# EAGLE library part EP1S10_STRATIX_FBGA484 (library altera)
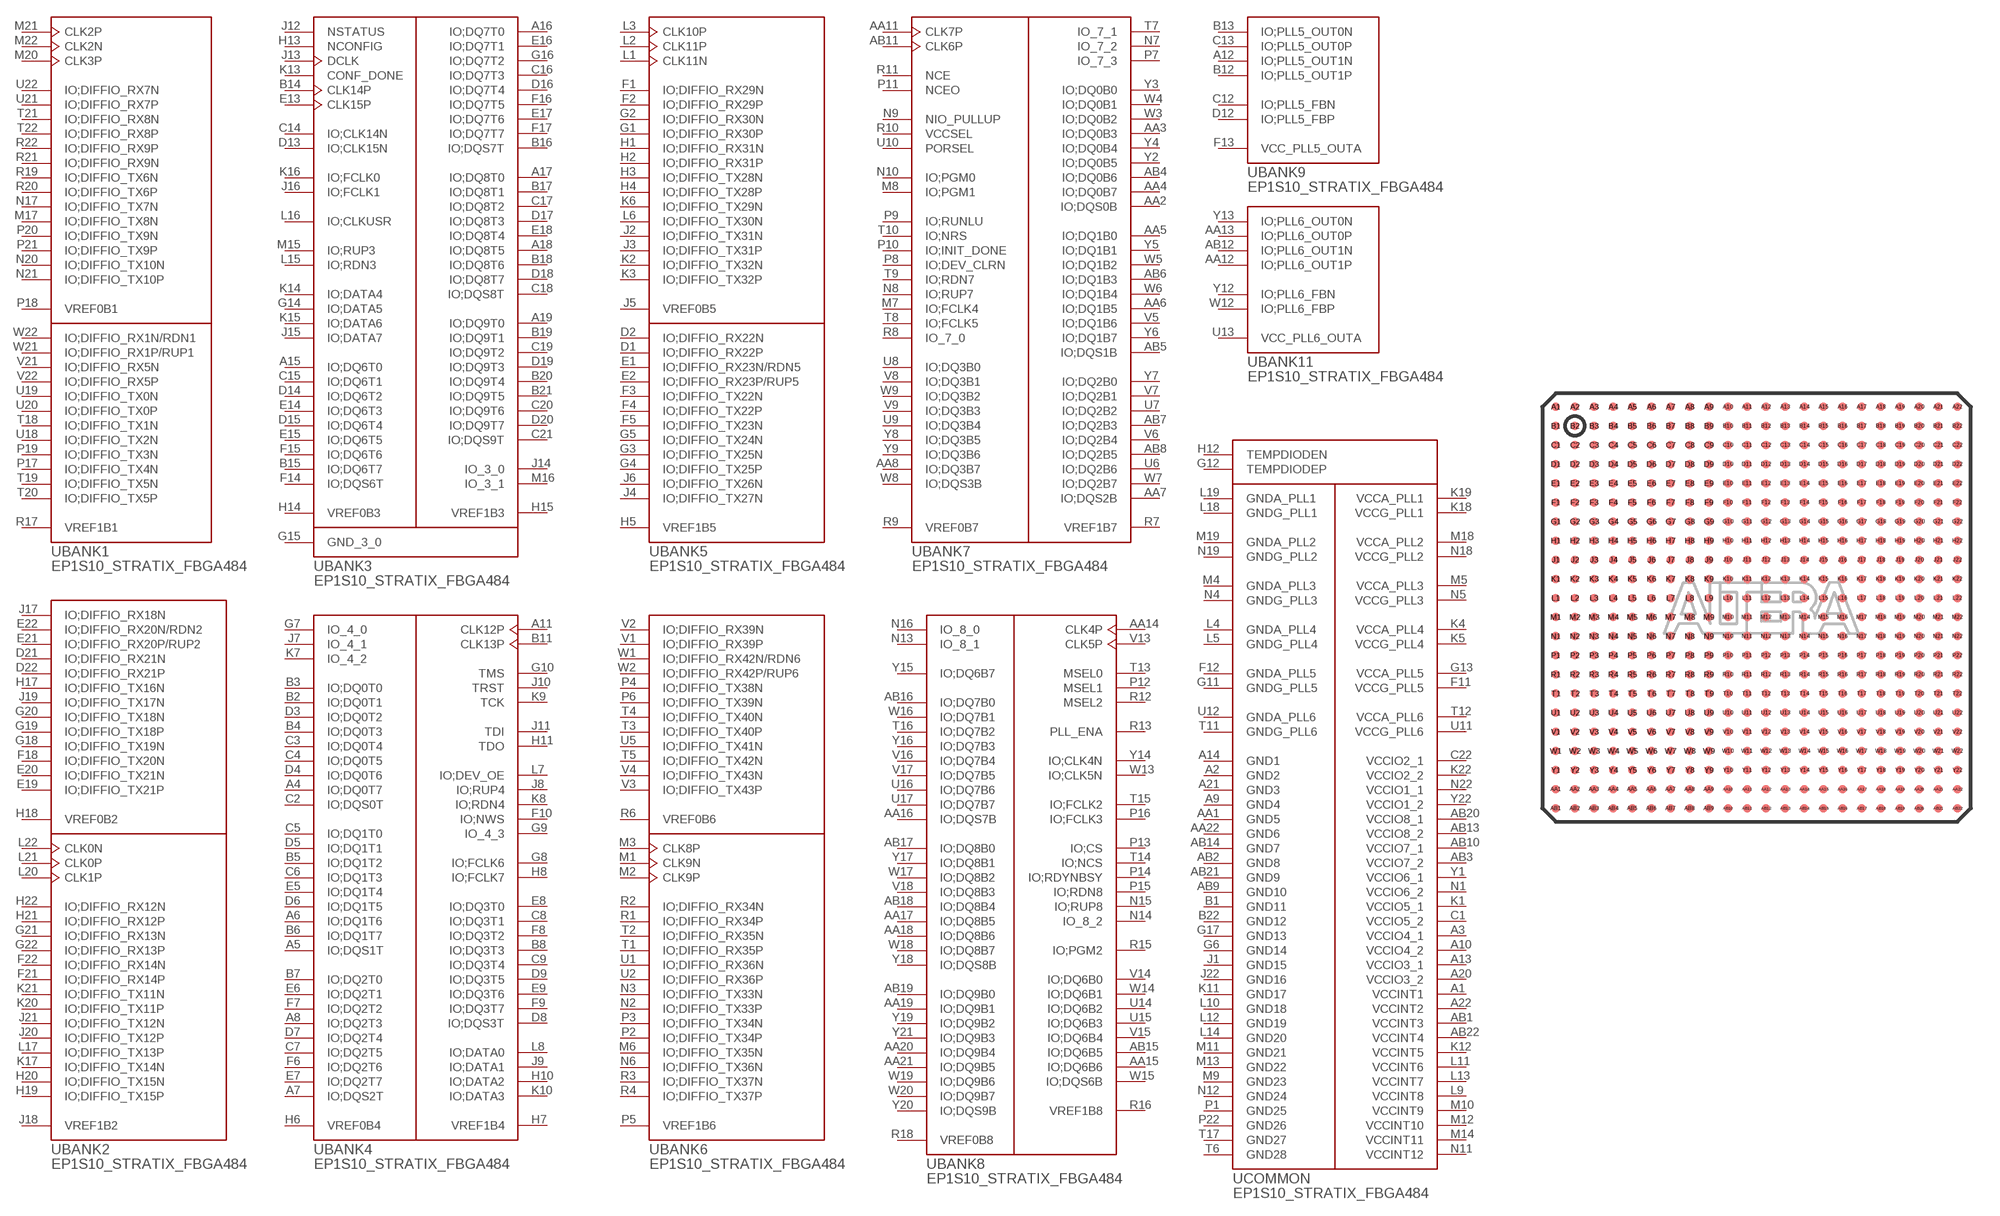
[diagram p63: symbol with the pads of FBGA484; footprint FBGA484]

Designator prefix -; gates COMMON=EP1S10_FBGA484_0 BANK1=EP1S10_FBGA484_1 BANK2=EP1S10_FBGA484_2 BANK3=EP1S10_FBGA484_3 BANK4=EP1S10_FBGA484_4 BANK5=EP1S10_FBGA484_5 BANK6=EP1S10_FBGA484_6 BANK7=EP1S10_FBGA484_7 BANK8=EP1S10_FBGA484_8 BANK9=EP1S10_FBGA484_9 BANK11=EP1S10_FBGA484_11 NC=EP1S10_FBGA484_NC

## EP1S10_STRATIX_FBGA484  [FBGA484]
A1  COMMON:VCCINT1  pwr
A2  COMMON:GND2  pwr
A3  COMMON:VCCIO4_1  pwr
A4  BANK4:IO;DQ0T7
A5  BANK4:IO;DQS1T
A6  BANK4:IO;DQ1T6
A7  BANK4:IO;DQS2T
A8  BANK4:IO;DQ2T3
A9  COMMON:GND4  pwr
A10  COMMON:VCCIO4_2  pwr
A11  BANK4:CLK12P  in
A12  BANK9:IO;PLL5_OUT1N
A13  COMMON:VCCIO3_1  pwr
A14  COMMON:GND1  pwr
A15  BANK3:IO;DQ6T0
A16  BANK3:IO;DQ7T0
A17  BANK3:IO;DQ8T0
A18  BANK3:IO;DQ8T5
A19  BANK3:IO;DQ9T0
A20  COMMON:VCCIO3_2  pwr
A21  COMMON:GND3  pwr
A22  COMMON:VCCINT2  pwr
AA1  COMMON:GND5  pwr
AA2  BANK7:IO;DQS0B
AA3  BANK7:IO;DQ0B3
AA4  BANK7:IO;DQ0B7
AA5  BANK7:IO;DQ1B0
AA6  BANK7:IO;DQ1B5
AA7  BANK7:IO;DQS2B
AA8  BANK7:IO;DQ3B7
AA9  NC:P$2  nc
AA10  NC:P$1  nc
AA11  BANK7:CLK7P  in
AA12  BANK11:IO;PLL6_OUT1P
AA13  BANK11:IO;PLL6_OUT0P
AA14  BANK8:CLK4P  in
AA15  BANK8:IO;DQ6B6
AA16  BANK8:IO;DQS7B
AA17  BANK8:IO;DQ8B5
AA18  BANK8:IO;DQ8B6
AA19  BANK8:IO;DQ9B1
AA20  BANK8:IO;DQ9B4
AA21  BANK8:IO;DQ9B5
AA22  COMMON:GND6  pwr
AB1  COMMON:VCCINT3  pwr
AB2  COMMON:GND8  pwr
AB3  COMMON:VCCIO7_2  pwr
AB4  BANK7:IO;DQ0B6
AB5  BANK7:IO;DQS1B
AB6  BANK7:IO;DQ1B3
AB7  BANK7:IO;DQ2B3
AB8  BANK7:IO;DQ2B5
AB9  COMMON:GND10  pwr
AB10  COMMON:VCCIO7_1  pwr
AB11  BANK7:CLK6P  in
AB12  BANK11:IO;PLL6_OUT1N
AB13  COMMON:VCCIO8_2  pwr
AB14  COMMON:GND7  pwr
AB15  BANK8:IO;DQ6B5
AB16  BANK8:IO;DQ7B0
AB17  BANK8:IO;DQ8B0
AB18  BANK8:IO;DQ8B4
AB19  BANK8:IO;DQ9B0
AB20  COMMON:VCCIO8_1  pwr
AB21  COMMON:GND9  pwr
AB22  COMMON:VCCINT4  pwr
B1  COMMON:GND11  pwr
B2  BANK4:IO;DQ0T1
B3  BANK4:IO;DQ0T0
B4  BANK4:IO;DQ0T3
B5  BANK4:IO;DQ1T2
B6  BANK4:IO;DQ1T7
B7  BANK4:IO;DQ2T0
B8  BANK4:IO;DQ3T3
B9  NC:P$4  nc
B10  NC:P$3  nc
B11  BANK4:CLK13P  in
B12  BANK9:IO;PLL5_OUT1P
B13  BANK9:IO;PLL5_OUT0N
B14  BANK3:CLK14P  in
B15  BANK3:IO;DQ6T7
B16  BANK3:IO;DQS7T
B17  BANK3:IO;DQ8T1
B18  BANK3:IO;DQ8T6
B19  BANK3:IO;DQ9T1
B20  BANK3:IO;DQ9T4
B21  BANK3:IO;DQ9T5
B22  COMMON:GND12  pwr
C1  COMMON:VCCIO5_2  pwr
C2  BANK4:IO;DQS0T
C3  BANK4:IO;DQ0T4
C4  BANK4:IO;DQ0T5
C5  BANK4:IO;DQ1T0
C6  BANK4:IO;DQ1T3
C7  BANK4:IO;DQ2T5
C8  BANK4:IO;DQ3T1
C9  BANK4:IO;DQ3T4
C10  NC:P$5  nc
C11  NC:P$6  nc
C12  BANK9:IO;PLL5_FBN
C13  BANK9:IO;PLL5_OUT0P
C14  BANK3:IO;CLK14N
C15  BANK3:IO;DQ6T1
C16  BANK3:IO;DQ7T3
C17  BANK3:IO;DQ8T2
C18  BANK3:IO;DQS8T
C19  BANK3:IO;DQ9T2
C20  BANK3:IO;DQ9T6
C21  BANK3:IO;DQS9T
C22  COMMON:VCCIO2_1  pwr
D1  BANK5:IO;DIFFIO_RX22P
D2  BANK5:IO;DIFFIO_RX22N
D3  BANK4:IO;DQ0T2
D4  BANK4:IO;DQ0T6
D5  BANK4:IO;DQ1T1
D6  BANK4:IO;DQ1T5
D7  BANK4:IO;DQ2T4
D8  BANK4:IO;DQS3T
D9  BANK4:IO;DQ3T5
D10  NC:P$7  nc
D11  NC:P$8  nc
D12  BANK9:IO;PLL5_FBP
D13  BANK3:IO;CLK15N
D14  BANK3:IO;DQ6T2
D15  BANK3:IO;DQ6T4
D16  BANK3:IO;DQ7T4
D17  BANK3:IO;DQ8T3
D18  BANK3:IO;DQ8T7
D19  BANK3:IO;DQ9T3
D20  BANK3:IO;DQ9T7
D21  BANK2:IO;DIFFIO_RX21N
D22  BANK2:IO;DIFFIO_RX21P
E1  BANK5:IO;DIFFIO_RX23N/RDN5
E2  BANK5:IO;DIFFIO_RX23P/RUP5
E3  NC:P$12  nc
E4  NC:P$13  nc
E5  BANK4:IO;DQ1T4
E6  BANK4:IO;DQ2T1
E7  BANK4:IO;DQ2T7
E8  BANK4:IO;DQ3T0
E9  BANK4:IO;DQ3T6
E10  NC:P$9  nc
E11  NC:P$10  nc
E12  NC:P$11  nc
E13  BANK3:CLK15P  in
E14  BANK3:IO;DQ6T3
E15  BANK3:IO;DQ6T5
E16  BANK3:IO;DQ7T1
E17  BANK3:IO;DQ7T6
E18  BANK3:IO;DQ8T4
E19  BANK2:IO;DIFFIO_TX21P
E20  BANK2:IO;DIFFIO_TX21N
E21  BANK2:IO;DIFFIO_RX20P/RUP2
E22  BANK2:IO;DIFFIO_RX20N/RDN2
F1  BANK5:IO;DIFFIO_RX29N
F2  BANK5:IO;DIFFIO_RX29P
F3  BANK5:IO;DIFFIO_TX22N
F4  BANK5:IO;DIFFIO_TX22P
F5  BANK5:IO;DIFFIO_TX23N
F6  BANK4:IO;DQ2T6
F7  BANK4:IO;DQ2T2
F8  BANK4:IO;DQ3T2
F9  BANK4:IO;DQ3T7
F10  BANK4:IO;NWS
F11  COMMON:VCCG_PLL5  pwr
F12  COMMON:GNDA_PLL5  pwr
F13  BANK9:VCC_PLL5_OUTA  pwr
F14  BANK3:IO;DQS6T
F15  BANK3:IO;DQ6T6
F16  BANK3:IO;DQ7T5
F17  BANK3:IO;DQ7T7
F18  BANK2:IO;DIFFIO_TX20N
F19  NC:P$14  nc
F20  NC:P$15  nc
F21  BANK2:IO;DIFFIO_RX14P
F22  BANK2:IO;DIFFIO_RX14N
G1  BANK5:IO;DIFFIO_RX30P
G2  BANK5:IO;DIFFIO_RX30N
G3  BANK5:IO;DIFFIO_TX25N
G4  BANK5:IO;DIFFIO_TX25P
G5  BANK5:IO;DIFFIO_TX24N
G6  COMMON:GND14  pwr
G7  BANK4:IO_4_0
G8  BANK4:IO;FCLK6
G9  BANK4:IO_4_3
G10  BANK4:TMS  in
G11  COMMON:GNDG_PLL5  pwr
G12  COMMON:TEMPDIODEP  in
G13  COMMON:VCCA_PLL5  pwr
G14  BANK3:IO;DATA5
G15  BANK3:GND_3_0  pwr
G16  BANK3:IO;DQ7T2
G17  COMMON:GND13  pwr
G18  BANK2:IO;DIFFIO_TX19N
G19  BANK2:IO;DIFFIO_TX18P
G20  BANK2:IO;DIFFIO_TX18N
G21  BANK2:IO;DIFFIO_RX13N
G22  BANK2:IO;DIFFIO_RX13P
H1  BANK5:IO;DIFFIO_RX31N
H2  BANK5:IO;DIFFIO_RX31P
H3  BANK5:IO;DIFFIO_TX28N
H4  BANK5:IO;DIFFIO_TX28P
H5  BANK5:VREF1B5  pwr
H6  BANK4:VREF0B4  pwr
H7  BANK4:VREF1B4  pwr
H8  BANK4:IO;FCLK7
H9  NC:P$17  nc
H10  BANK4:IO;DATA2
H11  BANK4:TDO  out
H12  COMMON:TEMPDIODEN  in
H13  BANK3:NCONFIG  in
H14  BANK3:VREF0B3  pwr
H15  BANK3:VREF1B3  pwr
H16  NC:P$16  nc
H17  BANK2:IO;DIFFIO_TX16N
H18  BANK2:VREF0B2  pwr
H19  BANK2:IO;DIFFIO_TX15P
H20  BANK2:IO;DIFFIO_TX15N
H21  BANK2:IO;DIFFIO_RX12P
H22  BANK2:IO;DIFFIO_RX12N
J1  COMMON:GND15  pwr
J2  BANK5:IO;DIFFIO_TX31N
J3  BANK5:IO;DIFFIO_TX31P
J4  BANK5:IO;DIFFIO_TX27N
J5  BANK5:VREF0B5  pwr
J6  BANK5:IO;DIFFIO_TX26N
J7  BANK4:IO_4_1
J8  BANK4:IO;RUP4
J9  BANK4:IO;DATA1
J10  BANK4:TRST  in
J11  BANK4:TDI  in
J12  BANK3:NSTATUS  oc
J13  BANK3:DCLK  in
J14  BANK3:IO_3_0
J15  BANK3:IO;DATA7
J16  BANK3:IO;FCLK1
J17  BANK2:IO;DIFFIO_RX18N
J18  BANK2:VREF1B2  pwr
J19  BANK2:IO;DIFFIO_TX17N
J20  BANK2:IO;DIFFIO_TX12P
J21  BANK2:IO;DIFFIO_TX12N
J22  COMMON:GND16  pwr
K1  COMMON:VCCIO5_1  pwr
K2  BANK5:IO;DIFFIO_TX32N
K3  BANK5:IO;DIFFIO_TX32P
K4  COMMON:VCCA_PLL4  pwr
K5  COMMON:VCCG_PLL4  pwr
K6  BANK5:IO;DIFFIO_TX29N
K7  BANK4:IO_4_2
K8  BANK4:IO;RDN4
K9  BANK4:TCK  in
K10  BANK4:IO;DATA3
K11  COMMON:GND17  pwr
K12  COMMON:VCCINT5  pwr
K13  BANK3:CONF_DONE  oc
K14  BANK3:IO;DATA4
K15  BANK3:IO;DATA6
K16  BANK3:IO;FCLK0
K17  BANK2:IO;DIFFIO_TX14N
K18  COMMON:VCCG_PLL1  pwr
K19  COMMON:VCCA_PLL1  pwr
K20  BANK2:IO;DIFFIO_TX11P
K21  BANK2:IO;DIFFIO_TX11N
K22  COMMON:VCCIO2_2  pwr
L1  BANK5:CLK11N
L2  BANK5:CLK11P  in
L3  BANK5:CLK10P  in
L4  COMMON:GNDA_PLL4  pwr
L5  COMMON:GNDG_PLL4  pwr
L6  BANK5:IO;DIFFIO_TX30N
L7  BANK4:IO;DEV_OE
L8  BANK4:IO;DATA0
L9  COMMON:VCCINT8  pwr
L10  COMMON:GND18  pwr
L11  COMMON:VCCINT6  pwr
L12  COMMON:GND19  pwr
L13  COMMON:VCCINT7  pwr
L14  COMMON:GND20  pwr
L15  BANK3:IO;RDN3
L16  BANK3:IO;CLKUSR
L17  BANK2:IO;DIFFIO_TX13P
L18  COMMON:GNDG_PLL1  pwr
L19  COMMON:GNDA_PLL1  pwr
L20  BANK2:CLK1P  in
L21  BANK2:CLK0P  in
L22  BANK2:CLK0N
M1  BANK6:CLK9N
M2  BANK6:CLK9P  in
M3  BANK6:CLK8P  in
M4  COMMON:GNDA_PLL3  pwr
M5  COMMON:VCCA_PLL3  pwr
M6  BANK6:IO;DIFFIO_TX35N
M7  BANK7:IO;FCLK4
M8  BANK7:IO;PGM1
M9  COMMON:GND23  pwr
M10  COMMON:VCCINT9  pwr
M11  COMMON:GND21  pwr
M12  COMMON:VCCINT10  pwr
M13  COMMON:GND22  pwr
M14  COMMON:VCCINT11  pwr
M15  BANK3:IO;RUP3
M16  BANK3:IO_3_1
M17  BANK1:IO;DIFFIO_TX8N
M18  COMMON:VCCA_PLL2  pwr
M19  COMMON:GNDA_PLL2  pwr
M20  BANK1:CLK3P  in
M21  BANK1:CLK2P  in
M22  BANK1:CLK2N  in
N1  COMMON:VCCIO6_2  pwr
N2  BANK6:IO;DIFFIO_TX33P
N3  BANK6:IO;DIFFIO_TX33N
N4  COMMON:GNDG_PLL3  pwr
N5  COMMON:VCCG_PLL3  pwr
N6  BANK6:IO;DIFFIO_TX36N
N7  BANK7:IO_7_2
N8  BANK7:IO;RUP7
N9  BANK7:NIO_PULLUP  in
N10  BANK7:IO;PGM0
N11  COMMON:VCCINT12  pwr
N12  COMMON:GND24  pwr
N13  BANK8:IO_8_1
N14  BANK8:IO_8_2
N15  BANK8:IO;RUP8
N16  BANK8:IO_8_0
N17  BANK1:IO;DIFFIO_TX7N
N18  COMMON:VCCG_PLL2  pwr
N19  COMMON:GNDG_PLL2  pwr
N20  BANK1:IO;DIFFIO_TX10N
N21  BANK1:IO;DIFFIO_TX10P
N22  COMMON:VCCIO1_1  pwr
P1  COMMON:GND25  pwr
P2  BANK6:IO;DIFFIO_TX34P
P3  BANK6:IO;DIFFIO_TX34N
P4  BANK6:IO;DIFFIO_TX38N
P5  BANK6:VREF1B6  pwr
P6  BANK6:IO;DIFFIO_TX39N
P7  BANK7:IO_7_3
P8  BANK7:IO;DEV_CLRN
P9  BANK7:IO;RUNLU
P10  BANK7:IO;INIT_DONE
P11  BANK7:NCEO  out
P12  BANK8:MSEL1  in
P13  BANK8:IO;CS
P14  BANK8:IO;RDYNBSY
P15  BANK8:IO;RDN8
P16  BANK8:IO;FCLK3
P17  BANK1:IO;DIFFIO_TX4N
P18  BANK1:VREF0B1  pwr
P19  BANK1:IO;DIFFIO_TX3N
P20  BANK1:IO;DIFFIO_TX9N
P21  BANK1:IO;DIFFIO_TX9P
P22  COMMON:GND26  pwr
R1  BANK6:IO;DIFFIO_RX34P
R2  BANK6:IO;DIFFIO_RX34N
R3  BANK6:IO;DIFFIO_TX37N
R4  BANK6:IO;DIFFIO_TX37P
R5  NC:P$19  nc
R6  BANK6:VREF0B6  pwr
R7  BANK7:VREF1B7  pwr
R8  BANK7:IO_7_0
R9  BANK7:VREF0B7  pwr
R10  BANK7:VCCSEL  in
R11  BANK7:NCE  in
R12  BANK8:MSEL2  in
R13  BANK8:PLL_ENA  in
R14  NC:P$18  nc
R15  BANK8:IO;PGM2
R16  BANK8:VREF1B8  pwr
R17  BANK1:VREF1B1  pwr
R18  BANK8:VREF0B8  pwr
R19  BANK1:IO;DIFFIO_TX6N
R20  BANK1:IO;DIFFIO_TX6P
R21  BANK1:IO;DIFFIO_RX9N
R22  BANK1:IO;DIFFIO_RX9P
T1  BANK6:IO;DIFFIO_RX35P
T2  BANK6:IO;DIFFIO_RX35N
T3  BANK6:IO;DIFFIO_TX40P
T4  BANK6:IO;DIFFIO_TX40N
T5  BANK6:IO;DIFFIO_TX42N
T6  COMMON:GND28  pwr
T7  BANK7:IO_7_1
T8  BANK7:IO;FCLK5
T9  BANK7:IO;RDN7
T10  BANK7:IO;NRS
T11  COMMON:GNDG_PLL6  pwr
T12  COMMON:VCCA_PLL6  pwr
T13  BANK8:MSEL0  in
T14  BANK8:IO;NCS
T15  BANK8:IO;FCLK2
T16  BANK8:IO;DQ7B2
T17  COMMON:GND27  pwr
T18  BANK1:IO;DIFFIO_TX1N
T19  BANK1:IO;DIFFIO_TX5N
T20  BANK1:IO;DIFFIO_TX5P
T21  BANK1:IO;DIFFIO_RX8N
T22  BANK1:IO;DIFFIO_RX8P
U1  BANK6:IO;DIFFIO_RX36N
U2  BANK6:IO;DIFFIO_RX36P
U3  NC:P$20  nc
U4  NC:P$21  nc
U5  BANK6:IO;DIFFIO_TX41N
U6  BANK7:IO;DQ2B6
U7  BANK7:IO;DQ2B2
U8  BANK7:IO;DQ3B0
U9  BANK7:IO;DQ3B4
U10  BANK7:PORSEL  in
U11  COMMON:VCCG_PLL6  pwr
U12  COMMON:GNDA_PLL6  pwr
U13  BANK11:VCC_PLL6_OUTA  pwr
U14  BANK8:IO;DQ6B2
U15  BANK8:IO;DQ6B3
U16  BANK8:IO;DQ7B6
U17  BANK8:IO;DQ7B7
U18  BANK1:IO;DIFFIO_TX2N
U19  BANK1:IO;DIFFIO_TX0N
U20  BANK1:IO;DIFFIO_TX0P
U21  BANK1:IO;DIFFIO_RX7P
U22  BANK1:IO;DIFFIO_RX7N
V1  BANK6:IO;DIFFIO_RX39P
V2  BANK6:IO;DIFFIO_RX39N
V3  BANK6:IO;DIFFIO_TX43P
V4  BANK6:IO;DIFFIO_TX43N
V5  BANK7:IO;DQ1B6
V6  BANK7:IO;DQ2B4
V7  BANK7:IO;DQ2B1
V8  BANK7:IO;DQ3B1
V9  BANK7:IO;DQ3B3
V10  NC:P$22  nc
V11  NC:P$23  nc
V12  NC:P$24  nc
V13  BANK8:CLK5P  in
V14  BANK8:IO;DQ6B0
V15  BANK8:IO;DQ6B4
V16  BANK8:IO;DQ7B4
V17  BANK8:IO;DQ7B5
V18  BANK8:IO;DQ8B3
V19  NC:P$25  nc
V20  NC:P$26  nc
V21  BANK1:IO;DIFFIO_RX5N
V22  BANK1:IO;DIFFIO_RX5P
W1  BANK6:IO;DIFFIO_RX42N/RDN6
W2  BANK6:IO;DIFFIO_RX42P/RUP6
W3  BANK7:IO;DQ0B2
W4  BANK7:IO;DQ0B1
W5  BANK7:IO;DQ1B2
W6  BANK7:IO;DQ1B4
W7  BANK7:IO;DQ2B7
W8  BANK7:IO;DQS3B
W9  BANK7:IO;DQ3B2
W10  NC:P$27  nc
W11  NC:P$28  nc
W12  BANK11:IO;PLL6_FBP
W13  BANK8:IO;CLK5N
W14  BANK8:IO;DQ6B1
W15  BANK8:IO;DQS6B
W16  BANK8:IO;DQ7B1
W17  BANK8:IO;DQ8B2
W18  BANK8:IO;DQ8B7
W19  BANK8:IO;DQ9B6
W20  BANK8:IO;DQ9B7
W21  BANK1:IO;DIFFIO_RX1P/RUP1
W22  BANK1:IO;DIFFIO_RX1N/RDN1
Y1  COMMON:VCCIO6_1  pwr
Y2  BANK7:IO;DQ0B5
Y3  BANK7:IO;DQ0B0
Y4  BANK7:IO;DQ0B4
Y5  BANK7:IO;DQ1B1
Y6  BANK7:IO;DQ1B7
Y7  BANK7:IO;DQ2B0
Y8  BANK7:IO;DQ3B5
Y9  BANK7:IO;DQ3B6
Y10  NC:P$29  nc
Y11  NC:P$30  nc
Y12  BANK11:IO;PLL6_FBN
Y13  BANK11:IO;PLL6_OUT0N
Y14  BANK8:IO;CLK4N
Y15  BANK8:IO;DQ6B7
Y16  BANK8:IO;DQ7B3
Y17  BANK8:IO;DQ8B1
Y18  BANK8:IO;DQS8B
Y19  BANK8:IO;DQ9B2
Y20  BANK8:IO;DQS9B
Y21  BANK8:IO;DQ9B3
Y22  COMMON:VCCIO1_2  pwr

## Footprint FBGA484 (pad centres in mm)
Fine Ball Grid Array
smd 0.45 x 0.45: A1 -10.5,10.5; A2 -9.5,10.5; A3 -8.5,10.5; A4 -7.5,10.5; A5 -6.5,10.5; A6 -5.5,10.5; A7 -4.5,10.5; A8 -3.5,10.5; A9 -2.5,10.5; A10 -1.5,10.5; A11 -0.5,10.5; A12 0.5,10.5; A13 1.5,10.5; A14 2.5,10.5; A15 3.5,10.5; A16 4.5,10.5; A17 5.5,10.5; A18 6.5,10.5; A19 7.5,10.5; A20 8.5,10.5; A21 9.5,10.5; A22 10.5,10.5; AA1 -10.5,-9.5; AA2 -9.5,-9.5; AA3 -8.5,-9.5; AA4 -7.5,-9.5; AA5 -6.5,-9.5; AA6 -5.5,-9.5; AA7 -4.5,-9.5; AA8 -3.5,-9.5; AA9 -2.5,-9.5; AA10 -1.5,-9.5; AA11 -0.5,-9.5; AA12 0.5,-9.5; AA13 1.5,-9.5; AA14 2.5,-9.5; AA15 3.5,-9.5; AA16 4.5,-9.5; AA17 5.5,-9.5; AA18 6.5,-9.5; AA19 7.5,-9.5; AA20 8.5,-9.5; AA21 9.5,-9.5; AA22 10.5,-9.5; AB1 -10.5,-10.5; AB2 -9.5,-10.5; AB3 -8.5,-10.5; AB4 -7.5,-10.5; AB5 -6.5,-10.5; AB6 -5.5,-10.5; AB7 -4.5,-10.5; AB8 -3.5,-10.5; AB9 -2.5,-10.5; AB10 -1.5,-10.5; AB11 -0.5,-10.5; AB12 0.5,-10.5; AB13 1.5,-10.5; AB14 2.5,-10.5; AB15 3.5,-10.5; AB16 4.5,-10.5; AB17 5.5,-10.5; AB18 6.5,-10.5; AB19 7.5,-10.5; AB20 8.5,-10.5; AB21 9.5,-10.5; AB22 10.5,-10.5; B1 -10.5,9.5; B2 -9.5,9.5; B3 -8.5,9.5; B4 -7.5,9.5; B5 -6.5,9.5; B6 -5.5,9.5; B7 -4.5,9.5; B8 -3.5,9.5; B9 -2.5,9.5; B10 -1.5,9.5; B11 -0.5,9.5; B12 0.5,9.5; B13 1.5,9.5; B14 2.5,9.5; B15 3.5,9.5; B16 4.5,9.5; B17 5.5,9.5; B18 6.5,9.5; B19 7.5,9.5; B20 8.5,9.5; B21 9.5,9.5; B22 10.5,9.5; C1 -10.5,8.5; C2 -9.5,8.5; C3 -8.5,8.5; C4 -7.5,8.5; C5 -6.5,8.5; C6 -5.5,8.5; C7 -4.5,8.5; C8 -3.5,8.5; C9 -2.5,8.5; C10 -1.5,8.5; C11 -0.5,8.5; C12 0.5,8.5; C13 1.5,8.5; C14 2.5,8.5; C15 3.5,8.5; C16 4.5,8.5; C17 5.5,8.5; C18 6.5,8.5; C19 7.5,8.5; C20 8.5,8.5; C21 9.5,8.5; C22 10.5,8.5; D1 -10.5,7.5; D2 -9.5,7.5; D3 -8.5,7.5; D4 -7.5,7.5; D5 -6.5,7.5; D6 -5.5,7.5; D7 -4.5,7.5; D8 -3.5,7.5; D9 -2.5,7.5; D10 -1.5,7.5; D11 -0.5,7.5; D12 0.5,7.5; D13 1.5,7.5; D14 2.5,7.5; D15 3.5,7.5; D16 4.5,7.5; D17 5.5,7.5; D18 6.5,7.5; D19 7.5,7.5; D20 8.5,7.5; D21 9.5,7.5; D22 10.5,7.5; E1 -10.5,6.5; E2 -9.5,6.5; E3 -8.5,6.5; E4 -7.5,6.5; E5 -6.5,6.5; E6 -5.5,6.5; E7 -4.5,6.5; E8 -3.5,6.5; E9 -2.5,6.5; E10 -1.5,6.5; E11 -0.5,6.5; E12 0.5,6.5; E13 1.5,6.5; E14 2.5,6.5; E15 3.5,6.5; E16 4.5,6.5; E17 5.5,6.5; E18 6.5,6.5; E19 7.5,6.5; E20 8.5,6.5; E21 9.5,6.5; E22 10.5,6.5; F1 -10.5,5.5; F2 -9.5,5.5; F3 -8.5,5.5; F4 -7.5,5.5; F5 -6.5,5.5; F6 -5.5,5.5; F7 -4.5,5.5; F8 -3.5,5.5; F9 -2.5,5.5; F10 -1.5,5.5; F11 -0.5,5.5; F12 0.5,5.5; F13 1.5,5.5; F14 2.5,5.5; F15 3.5,5.5; F16 4.5,5.5; F17 5.5,5.5; F18 6.5,5.5; F19 7.5,5.5; F20 8.5,5.5; F21 9.5,5.5; F22 10.5,5.5; G1 -10.5,4.5; G2 -9.5,4.5; G3 -8.5,4.5; G4 -7.5,4.5; G5 -6.5,4.5; G6 -5.5,4.5; G7 -4.5,4.5; G8 -3.5,4.5; G9 -2.5,4.5; G10 -1.5,4.5; G11 -0.5,4.5; G12 0.5,4.5; G13 1.5,4.5; G14 2.5,4.5; G15 3.5,4.5; G16 4.5,4.5; G17 5.5,4.5; G18 6.5,4.5; G19 7.5,4.5; G20 8.5,4.5; G21 9.5,4.5; G22 10.5,4.5; H1 -10.5,3.5; H2 -9.5,3.5; H3 -8.5,3.5; H4 -7.5,3.5; H5 -6.5,3.5; H6 -5.5,3.5; H7 -4.5,3.5; H8 -3.5,3.5; H9 -2.5,3.5; H10 -1.5,3.5; H11 -0.5,3.5; H12 0.5,3.5; H13 1.5,3.5; H14 2.5,3.5; H15 3.5,3.5; H16 4.5,3.5; H17 5.5,3.5; H18 6.5,3.5; H19 7.5,3.5; H20 8.5,3.5; H21 9.5,3.5; H22 10.5,3.5; J1 -10.5,2.5; J2 -9.5,2.5; J3 -8.5,2.5; J4 -7.5,2.5; J5 -6.5,2.5; J6 -5.5,2.5; J7 -4.5,2.5; J8 -3.5,2.5; J9 -2.5,2.5; J10 -1.5,2.5; J11 -0.5,2.5; J12 0.5,2.5; J13 1.5,2.5; J14 2.5,2.5; J15 3.5,2.5; J16 4.5,2.5; J17 5.5,2.5; J18 6.5,2.5; J19 7.5,2.5; J20 8.5,2.5; J21 9.5,2.5; J22 10.5,2.5; K1 -10.5,1.5; K2 -9.5,1.5; K3 -8.5,1.5; K4 -7.5,1.5; K5 -6.5,1.5; K6 -5.5,1.5; K7 -4.5,1.5; K8 -3.5,1.5; K9 -2.5,1.5; K10 -1.5,1.5; K11 -0.5,1.5; K12 0.5,1.5; K13 1.5,1.5; K14 2.5,1.5; K15 3.5,1.5; K16 4.5,1.5; K17 5.5,1.5; K18 6.5,1.5; K19 7.5,1.5; K20 8.5,1.5; K21 9.5,1.5; K22 10.5,1.5; L1 -10.5,0.5; L2 -9.5,0.5; L3 -8.5,0.5; L4 -7.5,0.5; L5 -6.5,0.5; L6 -5.5,0.5; L7 -4.5,0.5; L8 -3.5,0.5; L9 -2.5,0.5; L10 -1.5,0.5; L11 -0.5,0.5; L12 0.5,0.5; L13 1.5,0.5; L14 2.5,0.5; L15 3.5,0.5; L16 4.5,0.5; L17 5.5,0.5; L18 6.5,0.5; L19 7.5,0.5; L20 8.5,0.5; L21 9.5,0.5; L22 10.5,0.5; M1 -10.5,-0.5; M2 -9.5,-0.5; M3 -8.5,-0.5; M4 -7.5,-0.5; M5 -6.5,-0.5; M6 -5.5,-0.5; M7 -4.5,-0.5; M8 -3.5,-0.5; M9 -2.5,-0.5; M10 -1.5,-0.5; M11 -0.5,-0.5; M12 0.5,-0.5; M13 1.5,-0.5; M14 2.5,-0.5; M15 3.5,-0.5; M16 4.5,-0.5; M17 5.5,-0.5; M18 6.5,-0.5; M19 7.5,-0.5; M20 8.5,-0.5; M21 9.5,-0.5; M22 10.5,-0.5; N1 -10.5,-1.5; N2 -9.5,-1.5; N3 -8.5,-1.5; N4 -7.5,-1.5; N5 -6.5,-1.5; N6 -5.5,-1.5; N7 -4.5,-1.5; N8 -3.5,-1.5; N9 -2.5,-1.5; N10 -1.5,-1.5; N11 -0.5,-1.5; N12 0.5,-1.5; N13 1.5,-1.5; N14 2.5,-1.5; N15 3.5,-1.5; N16 4.5,-1.5; N17 5.5,-1.5; N18 6.5,-1.5; N19 7.5,-1.5; N20 8.5,-1.5; N21 9.5,-1.5; N22 10.5,-1.5; P1 -10.5,-2.5; P2 -9.5,-2.5; P3 -8.5,-2.5; P4 -7.5,-2.5; P5 -6.5,-2.5; P6 -5.5,-2.5; P7 -4.5,-2.5; P8 -3.5,-2.5; P9 -2.5,-2.5; P10 -1.5,-2.5; P11 -0.5,-2.5; P12 0.5,-2.5; P13 1.5,-2.5; P14 2.5,-2.5; P15 3.5,-2.5; P16 4.5,-2.5; P17 5.5,-2.5; P18 6.5,-2.5; P19 7.5,-2.5; P20 8.5,-2.5; P21 9.5,-2.5; P22 10.5,-2.5; R1 -10.5,-3.5; R2 -9.5,-3.5; R3 -8.5,-3.5; R4 -7.5,-3.5; R5 -6.5,-3.5; R6 -5.5,-3.5; R7 -4.5,-3.5; R8 -3.5,-3.5; R9 -2.5,-3.5; R10 -1.5,-3.5; R11 -0.5,-3.5; R12 0.5,-3.5; R13 1.5,-3.5; R14 2.5,-3.5; R15 3.5,-3.5; R16 4.5,-3.5; R17 5.5,-3.5; R18 6.5,-3.5; R19 7.5,-3.5; R20 8.5,-3.5; R21 9.5,-3.5; R22 10.5,-3.5; T1 -10.5,-4.5; T2 -9.5,-4.5; T3 -8.5,-4.5; T4 -7.5,-4.5; T5 -6.5,-4.5; T6 -5.5,-4.5; T7 -4.5,-4.5; T8 -3.5,-4.5; T9 -2.5,-4.5; T10 -1.5,-4.5; T11 -0.5,-4.5; T12 0.5,-4.5; T13 1.5,-4.5; T14 2.5,-4.5; T15 3.5,-4.5; T16 4.5,-4.5; T17 5.5,-4.5; T18 6.5,-4.5; T19 7.5,-4.5; T20 8.5,-4.5; T21 9.5,-4.5; T22 10.5,-4.5; U1 -10.5,-5.5; U2 -9.5,-5.5; U3 -8.5,-5.5; U4 -7.5,-5.5; U5 -6.5,-5.5; U6 -5.5,-5.5; U7 -4.5,-5.5; U8 -3.5,-5.5; U9 -2.5,-5.5; U10 -1.5,-5.5; U11 -0.5,-5.5; U12 0.5,-5.5; U13 1.5,-5.5; U14 2.5,-5.5; U15 3.5,-5.5; U16 4.5,-5.5; U17 5.5,-5.5; U18 6.5,-5.5; U19 7.5,-5.5; U20 8.5,-5.5; U21 9.5,-5.5; U22 10.5,-5.5; V1 -10.5,-6.5; V2 -9.5,-6.5; V3 -8.5,-6.5; V4 -7.5,-6.5; V5 -6.5,-6.5; V6 -5.5,-6.5; V7 -4.5,-6.5; V8 -3.5,-6.5; V9 -2.5,-6.5; V10 -1.5,-6.5; V11 -0.5,-6.5; V12 0.5,-6.5; V13 1.5,-6.5; V14 2.5,-6.5; V15 3.5,-6.5; V16 4.5,-6.5; V17 5.5,-6.5; V18 6.5,-6.5; V19 7.5,-6.5; V20 8.5,-6.5; V21 9.5,-6.5; V22 10.5,-6.5; W1 -10.5,-7.5; W2 -9.5,-7.5; W3 -8.5,-7.5; W4 -7.5,-7.5; W5 -6.5,-7.5; W6 -5.5,-7.5; W7 -4.5,-7.5; W8 -3.5,-7.5; W9 -2.5,-7.5; W10 -1.5,-7.5; W11 -0.5,-7.5; W12 0.5,-7.5; W13 1.5,-7.5; W14 2.5,-7.5; W15 3.5,-7.5; W16 4.5,-7.5; W17 5.5,-7.5; W18 6.5,-7.5; W19 7.5,-7.5; W20 8.5,-7.5; W21 9.5,-7.5; W22 10.5,-7.5; Y1 -10.5,-8.5; Y2 -9.5,-8.5; Y3 -8.5,-8.5; Y4 -7.5,-8.5; Y5 -6.5,-8.5; Y6 -5.5,-8.5; Y7 -4.5,-8.5; Y8 -3.5,-8.5; Y9 -2.5,-8.5; Y10 -1.5,-8.5; Y11 -0.5,-8.5; Y12 0.5,-8.5; Y13 1.5,-8.5; Y14 2.5,-8.5; Y15 3.5,-8.5; Y16 4.5,-8.5; Y17 5.5,-8.5; Y18 6.5,-8.5; Y19 7.5,-8.5; Y20 8.5,-8.5; Y21 9.5,-8.5; Y22 10.5,-8.5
